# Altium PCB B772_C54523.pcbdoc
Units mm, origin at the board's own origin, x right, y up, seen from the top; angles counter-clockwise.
Board outline 20.36 x 16.12 mm, 2 copper layers (Top Layer, Bottom Layer), stack 0 mm thick; 1 components, 0 nets, 3 pads, 0 vias.
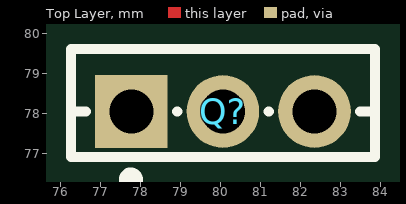
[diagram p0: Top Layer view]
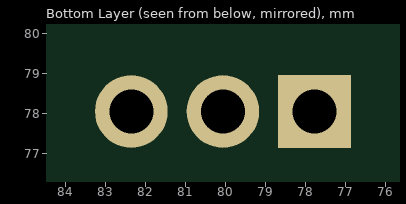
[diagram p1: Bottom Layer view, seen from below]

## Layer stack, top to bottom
Top Layer: signal copper (thickness not stored)
Bottom Layer: signal copper (thickness not stored)

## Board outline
90.21,69.85 69.85,69.85 69.85,85.965 90.21,85.965

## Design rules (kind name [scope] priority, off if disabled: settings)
PasteMaskExpansion "Paste Mask Expansion" [All] p1: expansion=0
SolderMaskExpansion "Solder Mask Expansion" [IsVia] p1: expansion=-25.4 istentingtop=TRUE
SolderMaskExpansion "Solder Mask Expansion" [All] p2: expansion=0.051 istentingtop=FALSE

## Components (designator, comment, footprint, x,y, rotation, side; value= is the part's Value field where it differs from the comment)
Q? "B772(RANGE:160-320)" TO-126-3_L7.6-W2.7-P2.30-L 80.06,78.05 r0 top

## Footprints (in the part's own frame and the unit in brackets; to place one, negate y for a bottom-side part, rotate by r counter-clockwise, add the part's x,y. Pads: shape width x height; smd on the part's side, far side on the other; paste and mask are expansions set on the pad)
TO-126-3_L7.6-W2.7-P2.30-L [mil]
  rect 71.5x71.5 hole 43.31: 1(-90.16,0)
  round 71.5 hole 43.31: 2(0,0) 3(90.16,0)
  silkscreen extent -150,-73 150,62

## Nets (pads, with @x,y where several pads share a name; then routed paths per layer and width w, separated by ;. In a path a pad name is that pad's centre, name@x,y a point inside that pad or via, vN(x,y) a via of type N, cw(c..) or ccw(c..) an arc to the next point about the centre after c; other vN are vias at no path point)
pads on no net: Q?.1 Q?.2 Q?.3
